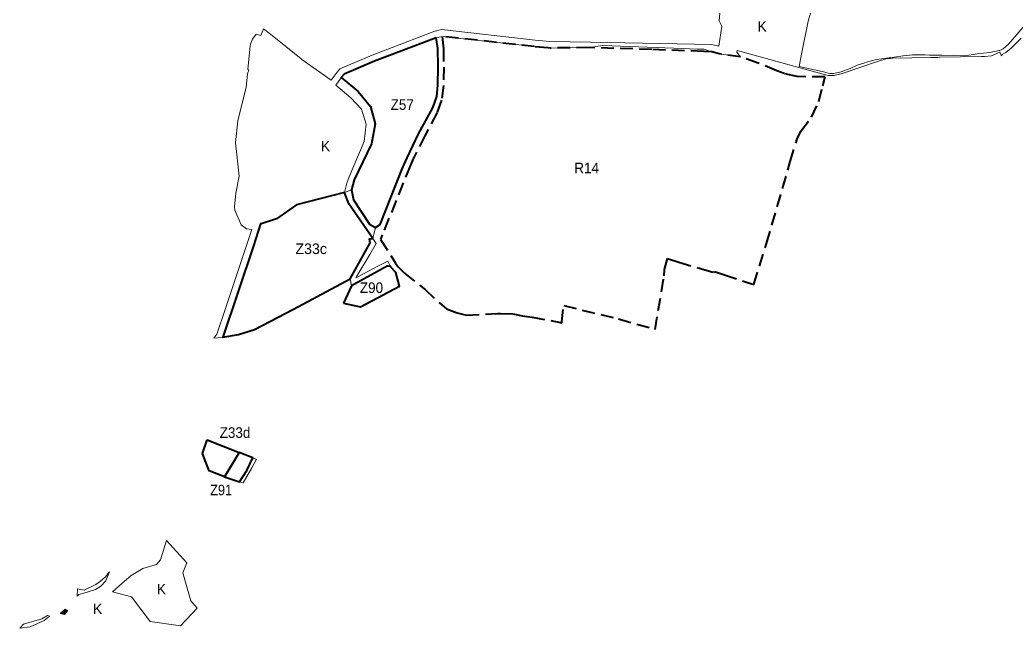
# Model space of a CAD drawing. Extents: x -650276 to -642489, y -1074311 to -1066658.
# Drawn here: x -648979 to -646724, y -1074311 to -1072934 of the extents above; entities that cross this region are included whole.
import ezdxf

# ---------------------------------------------------------------- set-up
doc = ezdxf.new("R2010")
doc.units = 0
doc.header["$LTSCALE"] = 9.6
doc.linetypes.add('MEDIUM_DASHED', pattern=[4.5, 3, -1.5])
for name, color, linetype, lineweight in [('44', 7, 'Continuous', 40), ('45', 7, 'Continuous', 40), ('46', 7, 'Continuous', 13), ('47', 7, 'Continuous', 13), ('48', 7, 'Continuous', 13), ('61', 7, 'MEDIUM_DASHED', 40), ('62', 7, 'Continuous', 35), ('63', 7, 'Continuous', 13)]:
    doc.layers.add(name, color=color, linetype=linetype, lineweight=lineweight)

msp = doc.modelspace()

# ---------------------------------------------------------------- hatches: boundary and pattern name
at = {"layer": '47'}
msp.add_hatch(color=256, dxfattribs=at).paths.add_polyline_path([(-648876.21, -1074268.73), (-648887.619, -1074278.134), (-648877.799, -1074280.64), (-648870.041, -1074271.932)])

# ---------------------------------------------------------------- linework, layer by layer
at = {"layer": '44'}
msp.add_line((-648245.341, -1073575.152), (-648207, -1073584), dxfattribs=at)
for points in [[(-648139.56, -1073491.4), (-648146.4, -1073491.55), (-648220.42, -1073532.43), (-648227.63, -1073535.89), (-648245.341, -1073575.152)], [(-648207, -1073584), (-648119, -1073537), (-648127.31, -1073505.75), (-648138.41, -1073493.62), (-648139.56, -1073491.4)]]:
    msp.add_lwpolyline(points, dxfattribs=at)
msp.add_lwpolyline([(-648515.333, -1073968.584), (-648480.86, -1073980.25), (-648464.44, -1073954.69), (-648451.05, -1073925.87), (-648481.749, -1073913.76), (-648498, -1073940)], close=True, dxfattribs=at)
at = {"layer": '45'}
for points in [[(-648030.86, -1073039.71), (-648032.09, -1072998.65), (-648035.592, -1072974.222), (-648175.061, -1073027.551), (-648244.214, -1073056.657), (-648250.491, -1073064.698), (-648212.22, -1073096.39), (-648184.37, -1073129.89)], [(-648030.86, -1073039.71), (-648032.09, -1072998.65), (-648035.592, -1072974.222), (-648175.061, -1073027.551), (-648244.214, -1073056.657), (-648250.491, -1073064.698), (-648212.22, -1073096.39), (-648184.37, -1073129.89)], [(-648101.67, -1073246.63), (-648075.34, -1073191.93), (-648043.29, -1073132.97), (-648034.43, -1073107.07), (-648031.8, -1073082.07), (-648030.86, -1073039.71)], [(-648101.67, -1073246.63), (-648075.34, -1073191.93), (-648043.29, -1073132.97), (-648034.43, -1073107.07), (-648031.8, -1073082.07), (-648030.86, -1073039.71)], [(-648184.37, -1073129.89), (-648174.03, -1073168.94), (-648182.12, -1073214.56), (-648221.39, -1073296.24), (-648227.75, -1073318.75), (-648223.03, -1073341.59), (-648186.47, -1073396.47), (-648173.38, -1073404.03)], [(-648184.37, -1073129.89), (-648174.03, -1073168.94), (-648182.12, -1073214.56), (-648221.39, -1073296.24), (-648227.75, -1073318.75), (-648223.03, -1073341.59), (-648186.47, -1073396.47), (-648173.38, -1073404.03)], [(-648173.38, -1073404.03), (-648162.55, -1073397.4), (-648112.36, -1073270.87), (-648101.67, -1073246.63)], [(-648173.38, -1073404.03), (-648162.55, -1073397.4), (-648112.36, -1073270.87), (-648101.67, -1073246.63)], [(-648272.642, -1073332.558), (-648352.312, -1073353), (-648397.062, -1073384.375)], [(-648272.642, -1073332.558), (-648352.312, -1073353), (-648397.062, -1073384.375)], [(-648179.07, -1073428.81), (-648233.36, -1073350.68), (-648243.08, -1073325.04), (-648272.642, -1073332.558)], [(-648179.07, -1073428.81), (-648233.36, -1073350.68), (-648243.08, -1073325.04), (-648272.642, -1073332.558)], [(-648397.062, -1073384.375), (-648432.187, -1073395.625), (-648433.206, -1073395.51), (-648449.599, -1073445.278)], [(-648397.062, -1073384.375), (-648432.187, -1073395.625), (-648433.206, -1073395.51), (-648449.599, -1073445.278)], [(-648447.06, -1073635.39), (-648358.69, -1073589.35), (-648230.81, -1073520.18), (-648185.34, -1073438.91), (-648185.82, -1073435.12), (-648186.46, -1073430.01), (-648183.46, -1073429.52), (-648179.07, -1073428.81)], [(-648447.06, -1073635.39), (-648358.69, -1073589.35), (-648230.81, -1073520.18), (-648185.34, -1073438.91), (-648185.82, -1073435.12), (-648186.46, -1073430.01), (-648183.46, -1073429.52), (-648179.07, -1073428.81)], [(-648449.599, -1073445.278), (-648518.867, -1073652.836), (-648483.58, -1073646.7), (-648447.06, -1073635.39), (-648447.06, -1073635.39)], [(-648449.599, -1073445.278), (-648518.867, -1073652.836), (-648483.58, -1073646.7), (-648447.06, -1073635.39), (-648447.06, -1073635.39)]]:
    msp.add_lwpolyline(points, dxfattribs=at)
msp.add_lwpolyline([(-648554.42, -1073885.092), (-648481.749, -1073913.76), (-648515.333, -1073968.584), (-648549.76, -1073954.86), (-648564.75, -1073915.91)], close=True, dxfattribs=at)
at = {"layer": '47'}
for points in [[(-647392.96, -1072918.277), (-647394.87, -1072936.08), (-647388.62, -1072948.03), (-647395.47, -1072993.25), (-647411.293, -1072989.813), (-647411.294, -1072989.813), (-647411.294, -1072989.813), (-647411.298, -1072989.813), (-647685.748, -1072984.544), (-647778.296, -1072982.767), (-647811.752, -1072979.4), (-648023.495, -1072955.875), (-648023.498, -1072955.876), (-648023.818, -1072955.949), (-648037.595, -1072959.123), (-648038.877, -1072959.418), (-648180.651, -1073013.629), (-648253.635, -1073044.348), (-648261.902, -1073054.939), (-648273.756, -1073070.132), (-648273.756, -1073070.132), (-648339.58, -1073023.82), (-648341.495, -1073022.285), (-648411.09, -1072966.5), (-648426.547, -1072954.108)], [(-646692.432, -1072934.135), (-646739.241, -1072988.798), (-646751.061, -1072999.106), (-646758.883, -1073002.885), (-646760.416, -1073003.25), (-646781.703, -1073007.452), (-646809.778, -1073011.019), (-646838.25, -1073014.938), (-646861.07, -1073014.672), (-646890.523, -1073014.073), (-646904.131, -1073013.793), (-646914.796, -1073013.573), (-646918.156, -1073013.511), (-646928.807, -1073013.313), (-646956.919, -1073012.775), (-646978.077, -1073014.931), (-646997.824, -1073018.092), (-647006.715, -1073019.236), (-647009.402, -1073019.582), (-647026.763, -1073021.811), (-647037.971, -1073023.24), (-647060.677, -1073029.351), (-647064.784, -1073030.747), (-647082.267, -1073036.684), (-647097.466, -1073044.268), (-647118.513, -1073051.327), (-647134.596, -1073054.974), (-647143.312, -1073055.421), (-647147.85, -1073054.204), (-647152.621, -1073052.925), (-647154.999, -1073052.287), (-647161.068, -1073050.946), (-647161.068, -1073050.946), (-647161.068, -1073050.946), (-647213.218, -1073039.42), (-647213.562, -1073039.322), (-647210.396, -1073023.593), (-647207.176, -1073007.598), (-647192.93, -1072936.82), (-647187.445, -1072918.804)], [(-648426.547, -1072954.108), (-648432.527, -1072969.463), (-648443.591, -1072965.983), (-648451.657, -1072977.25), (-648456.2, -1072989.149), (-648457.123, -1072993.118), (-648461.979, -1073045.585), (-648460.355, -1073048.753), (-648461.973, -1073052.688), (-648463.036, -1073057.011), (-648465.708, -1073085.876), (-648484.661, -1073162.812), (-648490.539, -1073212.35), (-648481.853, -1073287.675), (-648489.355, -1073326.567), (-648492.485, -1073357.358), (-648491.34, -1073364.805), (-648477.028, -1073398.055), (-648464.929, -1073407.031), (-648453.228, -1073408.349), (-648463.838, -1073440.559), (-648513.627, -1073589.927), (-648532.252, -1073645.567), (-648539.599, -1073654.802), (-648531.31, -1073654.08), (-648522.79, -1073653.23), (-648518.867, -1073652.836), (-648499.399, -1073594.679), (-648449.599, -1073445.278), (-648433.206, -1073395.51), (-648432.187, -1073395.625), (-648397.062, -1073384.375), (-648378.125, -1073370.875), (-648352.312, -1073353), (-648314.687, -1073343.25), (-648272.642, -1073332.558), (-648243.08, -1073325.04), (-648237.98, -1073303.4), (-648232.64, -1073289.31), (-648198.7, -1073209.08), (-648194.2, -1073170.13), (-648205.04, -1073136.07), (-648228.91, -1073110.54), (-648262.917, -1073081.543), (-648251.027, -1073065.418), (-648250.491, -1073064.698), (-648244.214, -1073056.657), (-648175.061, -1073027.551), (-648035.592, -1072974.222), (-648022.279, -1072971.102), (-647813.331, -1072994.317), (-647782.72, -1072997.397), (-647777.337, -1072997.711), (-647689.11, -1072996.49), (-647658.437, -1072991.865), (-647658.437, -1072991.865), (-647658.437, -1072991.865), (-647658.437, -1072991.865), (-647658.437, -1072991.865), (-647658.437, -1072991.865), (-647497.35, -1072997.93), (-647444.42, -1072999.87), (-647429.276, -1073000.424), (-647411.34, -1073005.89), (-647394.782, -1073011.002), (-647346.22, -1073017.52), (-647354.76, -1073006.65), (-647353.78, -1073003.1), (-647213.99, -1073041.449), (-647153.44, -1073058.06), (-647152.96, -1073058.19), (-647147.91, -1073059.64), (-647147.43, -1073059.78), (-647147.17, -1073059.97), (-647134.03, -1073059.94), (-647118.27, -1073055.88), (-647033.44, -1073027.43), (-647028.91, -1073025.91), (-647026.54, -1073025.11), (-647013.4, -1073021.42), (-647006.15, -1073020.99), (-647001.66, -1073020.72), (-646914.54, -1073019), (-646913.94, -1073018.99), (-646899.22, -1073018.7), (-646895.76, -1073018.63), (-646800.44, -1073016.74), (-646793.8, -1073016.61), (-646777.74, -1073015.29), (-646758.545, -1073007.234), (-646755.58, -1073013.43), (-646754.581, -1073015.554)], [(-646754.581, -1073015.554), (-646753.573, -1073012.306), (-646744.92, -1073007.46), (-646732.95, -1072998.07), (-646710.3, -1072975.31)], [(-648833.449, -1074232.685), (-648807.065, -1074223.704), (-648794.902, -1074216.219), (-648783.863, -1074204.056), (-648775.93, -1074183.91), (-648784.8, -1074195.26), (-648795.65, -1074205.35), (-648806.55, -1074212.62), (-648833.11, -1074225.2), (-648844.05, -1074223.24), (-648848.28, -1074222.49), (-648848.696, -1074238.993)], [(-648848.696, -1074238.993), (-648845.424, -1074235.305), (-648833.449, -1074232.685)]]:
    msp.add_lwpolyline(points, dxfattribs=at)
for points in [[(-648725.93, -1074240.58), (-648683.5, -1074296.12), (-648683.5, -1074296.12), (-648614.6, -1074306.17), (-648577.25, -1074266.06), (-648591.67, -1074249.72), (-648609.49, -1074186.61), (-648600.53, -1074163.47), (-648646.42, -1074113.19), (-648660.16, -1074156.75), (-648669.01, -1074167.27), (-648700.45, -1074176.73), (-648726.23, -1074192.02), (-648747.74, -1074210.12), (-648768.94, -1074229.25)], [(-648978.575, -1074311.426), (-648955.265, -1074308.325), (-648923.698, -1074294.313), (-648912.63, -1074284.912), (-648910.988, -1074284.211), (-648915.73, -1074283.08), (-648929.03, -1074290.14), (-648970.3, -1074302.9)], [(-648876.21, -1074268.73), (-648887.619, -1074278.134), (-648877.799, -1074280.64), (-648870.041, -1074271.932)]]:
    msp.add_lwpolyline(points, close=True, dxfattribs=at)
at = {"layer": '61'}
msp.add_lwpolyline([(-648019.38, -1072999.62), (-648018.59, -1073040.65), (-648019.04, -1073082.7), (-648023.38, -1073115.63), (-648033.71, -1073143.76), (-648060.75, -1073194.72), (-648088.41, -1073249.9), (-648094.092, -1073263.034), (-648157.74, -1073420.89), (-648161.7, -1073431.46), (-648127.64, -1073484.76), (-648122.58, -1073492.69), (-648107.53, -1073507.68), (-648060.92, -1073544.52), (-648027.7, -1073575.75), (-648012.55, -1073588.03), (-647987.9, -1073597.16), (-647967.15, -1073602.95), (-647896.59, -1073598.78), (-647889.64, -1073598.65), (-647861.92, -1073599.87), (-647840.12, -1073604.27), (-647818.3, -1073607.2), (-647751.31, -1073619.66), (-647751.124, -1073618.122), (-647746.63, -1073580.97), (-647622.63, -1073611.03), (-647539.83, -1073634.79), (-647519.11, -1073513.63), (-647518.27, -1073499.08), (-647511.932, -1073474.5), (-647486.04, -1073482.326), (-647436.7, -1073497.24), (-647406.33, -1073506.42), (-647405.5, -1073503.75), (-647382.45, -1073511.28), (-647316.269, -1073532.9), (-647287.03, -1073440.3), (-647233.5, -1073254.63), (-647218, -1073203.36), (-647216.34, -1073199.89), (-647209.63, -1073185.84), (-647185.73, -1073154.33), (-647168.83, -1073118.8), (-647159.72, -1073083.31), (-647154.77, -1073062.68), (-647218.06, -1073062.37), (-647247.46, -1073055.63), (-647263.8, -1073049), (-647305.94, -1073031.89), (-647346.22, -1073017.52), (-647394.782, -1073011.002), (-647411.34, -1073005.89), (-647429.65, -1073005.19), (-647547.02, -1073001.04), (-647689.11, -1072996.49), (-647777.336, -1072997.711), (-647782.72, -1072997.397), (-647813.331, -1072994.317), (-648022.279, -1072971.102)], close=True, dxfattribs=at)
at = {"layer": '63'}
for points in [[(-648171.18, -1073440.16), (-648179.07, -1073428.81), (-648173.38, -1073404.03), (-648162.55, -1073397.4), (-648101.67, -1073246.63), (-648075.34, -1073191.93), (-648043.29, -1073132.97), (-648034.43, -1073107.07), (-648031.8, -1073082.07), (-648030.86, -1073039.71), (-648032.09, -1072998.65), (-648035.592, -1072974.222), (-648175.061, -1073027.551), (-648244.214, -1073056.657), (-648250.491, -1073064.698), (-648212.22, -1073096.39), (-648184.37, -1073129.89), (-648174.03, -1073168.94), (-648182.12, -1073214.56), (-648221.39, -1073296.24), (-648227.75, -1073318.75), (-648243.08, -1073325.04), (-648272.642, -1073332.558), (-648314.687, -1073343.25), (-648352.312, -1073353), (-648397.062, -1073384.375), (-648432.187, -1073395.625), (-648433.206, -1073395.51), (-648449.599, -1073445.278), (-648518.867, -1073652.836)], [(-648217.71, -1073518.22), (-648214.31, -1073512.51), (-648186.19, -1073465.35), (-648171.18, -1073440.16)], [(-648447.06, -1073635.39), (-648358.69, -1073589.35), (-648230.81, -1073520.18), (-648227.63, -1073535.89), (-648245.341, -1073575.152), (-648207, -1073584), (-648119, -1073537), (-648127.31, -1073505.75), (-648138.41, -1073493.62), (-648145.31, -1073480.31)], [(-648145.31, -1073480.31), (-648148.27, -1073481.86), (-648167.68, -1073492.02), (-648211.86, -1073515.16), (-648217.71, -1073518.22)], [(-648518.867, -1073652.836), (-648514.23, -1073652.37), (-648483.58, -1073646.7), (-648447.06, -1073635.39)], [(-648442.558, -1073929.22), (-648451.05, -1073925.87), (-648471, -1073918), (-648481.749, -1073913.76), (-648551.754, -1073886.144), (-648554.42, -1073885.092), (-648564.75, -1073915.91), (-648549.76, -1073954.86), (-648499.84, -1073974.76), (-648499.84, -1073974.76)], [(-648472.624, -1073982.632), (-648453.11, -1073948.16), (-648447.77, -1073938.64), (-648443.35, -1073930.53), (-648442.558, -1073929.22)], [(-648499.84, -1073974.76), (-648480.86, -1073980.25), (-648480.86, -1073980.25), (-648472.624, -1073982.632)]]:
    msp.add_lwpolyline(points, dxfattribs=at)

# ---------------------------------------------------------------- texts
at = {"layer": '44'}
for s, width, p in [('Z90', 0.95, (-648208.451, -1073552.422)), ('Z90', 0.95, (-648208.451, -1073552.422)), ('Z91', 0.9, (-648547.629, -1074010.653))]:
    msp.add_text(s, height=24, dxfattribs=dict(at, width=width)).set_placement(p)
at = {"layer": '46', "width": 0.95}
for s, p in [('Z57', (-648138.747, -1073137.744)), ('Z57', (-648138.747, -1073137.744)), ('Z33d', (-648525.981, -1073880.565))]:
    msp.add_text(s, height=24, dxfattribs=at).set_placement(p)
at = {"layer": '46'}
msp.add_text('Z33c', height=24, dxfattribs=at).set_placement((-648354.418, -1073464.218))
msp.add_text('Z33c', height=24, dxfattribs=at).set_placement((-648354.418, -1073464.218))
at = {"layer": '48'}
for p in [(-647307.985, -1072960.845), (-647307.985, -1072960.845), (-648296.955, -1073231.892), (-648668.641, -1074235.329), (-648812.985, -1074279.86)]:
    msp.add_text('K', height=24, dxfattribs=at).set_placement(p)
at = {"layer": '62', "width": 0.95}
msp.add_text('R14', height=24, dxfattribs=at).set_placement((-647722.71, -1073281.294))

doc.saveas('drawing.dxf')
